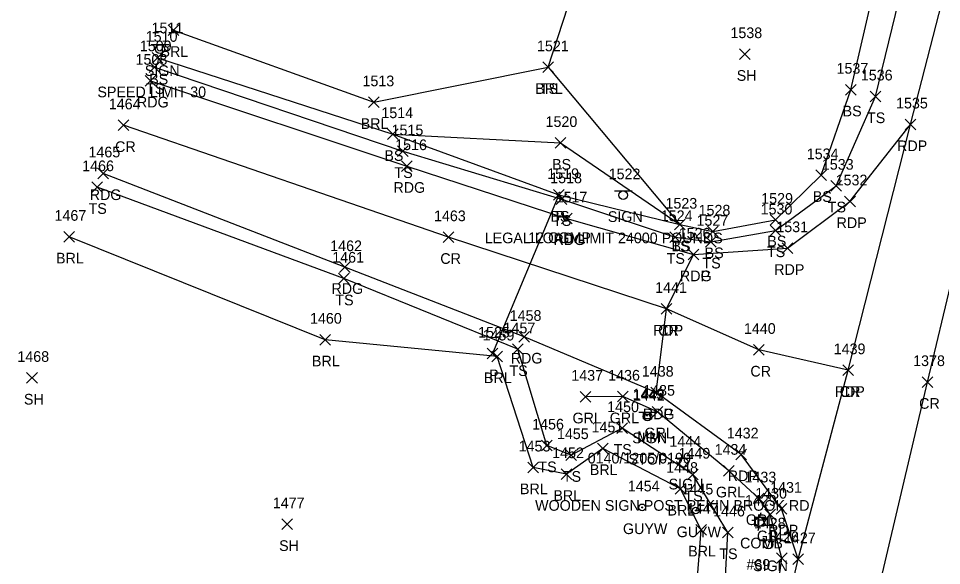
# Model space of a CAD drawing. Extents: x 1654425 to 1656893, y 667839 to 678429.
# Drawn here: x 1654452.9 to 1654625.8, y 668426.8 to 668529.4 of the extents above; entities that cross this region are included whole.
import ezdxf

# ---------------------------------------------------------------- set-up
doc = ezdxf.new("R2010")
doc.units = 0
for name, color, linetype in [('D_A', 7, 'Continuous'), ('D_I', 7, 'Continuous'), ('D_TIC', 7, 'Continuous'), ('DCP', 7, 'Continuous'), ('L_A', 7, 'Continuous'), ('L_C', 7, 'Continuous'), ('L_I', 7, 'Continuous'), ('L_TIC', 7, 'Continuous'), ('LABL', 7, 'Continuous'), ('LELB', 7, 'Continuous'), ('P_A', 7, 'Continuous'), ('P_I', 7, 'Continuous'), ('P_TIC', 7, 'Continuous'), ('PET', 7, 'Continuous'), ('PEU', 7, 'Continuous'), ('PRC', 7, 'Continuous'), ('R_A', 7, 'Continuous'), ('R_I', 7, 'Continuous'), ('R_TIC', 7, 'Continuous'), ('RGR', 7, 'Continuous'), ('S_A', 7, 'Continuous'), ('S_C', 7, 'Continuous'), ('S_I', 7, 'Continuous'), ('SRM', 7, 'Continuous'), ('SSGN', 7, 'Continuous'), ('U_A', 7, 'Continuous'), ('U_C', 7, 'Continuous'), ('U_I', 7, 'Continuous'), ('UP', 7, 'Continuous'), ('UPGW', 7, 'Continuous')]:
    doc.layers.add(name, color=color, linetype=linetype)

msp = doc.modelspace()

# ---------------------------------------------------------------- linework, layer by layer
at = {"layer": 'D_TIC'}
for points in [[(1654553.1, 668495.3), (1654555.1, 668497.3)], [(1654555.1, 668495.3), (1654553.1, 668497.3)], [(1654540.69, 668465.57), (1654542.69, 668467.57)], [(1654542.69, 668465.57), (1654540.69, 668467.57)]]:
    msp.add_lwpolyline(points, dxfattribs=at)
at = {"layer": 'DCP'}
msp.add_lwpolyline([(1654554.1, 668496.3), (1654541.69, 668466.57)], dxfattribs=at)
at = {"layer": 'L_TIC'}
for points in [[(1654480.96, 668526.19), (1654482.96, 668528.19)], [(1654482.96, 668526.19), (1654480.96, 668528.19)], [(1654477.94, 668521.02), (1654479.94, 668523.02)], [(1654479.94, 668521.02), (1654477.94, 668523.02)], [(1654587.96, 668521.7), (1654589.96, 668523.7)], [(1654589.96, 668521.7), (1654587.96, 668523.7)], [(1654477.4, 668519.24), (1654479.4, 668521.24)], [(1654479.4, 668519.24), (1654477.4, 668521.24)], [(1654551.15, 668519.24), (1654553.15, 668521.24)], [(1654553.15, 668519.24), (1654551.15, 668521.24)], [(1654551.15, 668519.24), (1654553.15, 668521.24)], [(1654553.15, 668519.24), (1654551.15, 668521.24)], [(1654607.84, 668515.04), (1654609.84, 668517.04)], [(1654609.84, 668515.04), (1654607.84, 668517.04)], [(1654612.45, 668513.77), (1654614.45, 668515.77)], [(1654614.45, 668513.77), (1654612.45, 668515.77)], [(1654518.46, 668512.68), (1654520.46, 668514.68)], [(1654520.46, 668512.68), (1654518.46, 668514.68)], [(1654522, 668506.7), (1654524, 668508.7)], [(1654524, 668506.7), (1654522, 668508.7)], [(1654522, 668506.7), (1654524, 668508.7)], [(1654524, 668506.7), (1654522, 668508.7)], [(1654553.42, 668505.05), (1654555.42, 668507.05)], [(1654555.42, 668505.05), (1654553.42, 668507.05)], [(1654523.92, 668503.49), (1654525.92, 668505.49)], [(1654525.92, 668503.49), (1654523.92, 668505.49)], [(1654602.26, 668499.01), (1654604.26, 668501.01)], [(1654604.26, 668499.01), (1654602.26, 668501.01)], [(1654466.62, 668496.76), (1654468.62, 668498.76)], [(1654468.62, 668496.76), (1654466.62, 668498.76)], [(1654605.09, 668497.04), (1654607.09, 668499.04)], [(1654607.09, 668497.04), (1654605.09, 668499.04)], [(1654553.1, 668495.3), (1654555.1, 668497.3)], [(1654555.1, 668495.3), (1654553.1, 668497.3)], [(1654553.63, 668494.51), (1654555.63, 668496.51)], [(1654555.63, 668494.51), (1654553.63, 668496.51)], [(1654575.79, 668489.74), (1654577.79, 668491.74)], [(1654577.79, 668489.74), (1654575.79, 668491.74)], [(1654575.79, 668489.74), (1654577.79, 668491.74)], [(1654577.79, 668489.74), (1654575.79, 668491.74)], [(1654575.79, 668489.74), (1654577.79, 668491.74)], [(1654577.79, 668489.74), (1654575.79, 668491.74)], [(1654593.74, 668490.66), (1654595.74, 668492.66)], [(1654595.74, 668490.66), (1654593.74, 668492.66)], [(1654582, 668488.45), (1654584, 668490.45)], [(1654584, 668488.45), (1654582, 668490.45)], [(1654593.71, 668488.65), (1654595.71, 668490.65)], [(1654595.71, 668488.65), (1654593.71, 668490.65)], [(1654461.39, 668487.47), (1654463.39, 668489.47)], [(1654463.39, 668487.47), (1654461.39, 668489.47)], [(1654574.92, 668487.4), (1654576.92, 668489.4)], [(1654576.92, 668487.4), (1654574.92, 668489.4)], [(1654581.62, 668486.53), (1654583.62, 668488.53)], [(1654583.62, 668486.53), (1654581.62, 668488.53)], [(1654512.85, 668479.62), (1654514.85, 668481.62)], [(1654514.85, 668479.62), (1654512.85, 668481.62)], [(1654509.33, 668468.18), (1654511.33, 668470.18)], [(1654511.33, 668468.18), (1654509.33, 668470.18)], [(1654545.47, 668466.37), (1654547.47, 668468.37)], [(1654547.47, 668466.37), (1654545.47, 668468.37)], [(1654541.55, 668465.03), (1654543.55, 668467.03)], [(1654543.55, 668465.03), (1654541.55, 668467.03)], [(1654454.43, 668461.02), (1654456.43, 668463.02)], [(1654456.43, 668461.02), (1654454.43, 668463.02)], [(1654564.96, 668451.6), (1654566.96, 668453.6)], [(1654566.96, 668451.6), (1654564.96, 668453.6)], [(1654550.88, 668448.34), (1654552.88, 668450.34)], [(1654552.88, 668448.34), (1654550.88, 668450.34)], [(1654561.38, 668447.81), (1654563.38, 668449.81)], [(1654563.38, 668447.81), (1654561.38, 668449.81)], [(1654555.46, 668446.54), (1654557.46, 668448.54)], [(1654557.46, 668446.54), (1654555.46, 668448.54)], [(1654548.29, 668444.22), (1654550.29, 668446.22)], [(1654550.29, 668444.22), (1654548.29, 668446.22)], [(1654554.56, 668442.97), (1654556.56, 668444.97)], [(1654556.56, 668442.97), (1654554.56, 668444.97)], [(1654578.25, 668442.89), (1654580.25, 668444.89)], [(1654580.25, 668442.89), (1654578.25, 668444.89)], [(1654575.94, 668440.22), (1654577.94, 668442.22)], [(1654577.94, 668440.22), (1654575.94, 668442.22)], [(1654502.23, 668433.58), (1654504.23, 668435.58)], [(1654504.23, 668433.58), (1654502.23, 668435.58)], [(1654579.8, 668432.54), (1654581.8, 668434.54)], [(1654581.8, 668432.54), (1654579.8, 668434.54)], [(1654584.78, 668432.05), (1654586.78, 668434.05)], [(1654586.78, 668432.05), (1654584.78, 668434.05)]]:
    msp.add_lwpolyline(points, dxfattribs=at)
at = {"layer": 'LABL'}
for points in [[(1654481.96, 668527.19), (1654519.46, 668513.68), (1654552.15, 668520.24), (1654557.67, 668537.4), (1654558.31, 668556.77)], [(1654577.73, 668393.9), (1654580.8, 668433.54), (1654576.94, 668441.22), (1654562.38, 668448.81), (1654555.56, 668443.97), (1654549.29, 668445.22), (1654542.55, 668466.03), (1654510.33, 668469.18), (1654462.39, 668488.47)]]:
    msp.add_lwpolyline(points, dxfattribs=at)
at = {"layer": 'LELB'}
for points in [[(1654478.4, 668520.24), (1654524.92, 668504.49), (1654554.63, 668495.51), (1654575.92, 668488.4), (1654582.62, 668487.53), (1654594.71, 668489.65), (1654606.09, 668498.04), (1654613.45, 668514.77), (1654621.57, 668548.1)], [(1654478.94, 668522.02), (1654523, 668507.7), (1654554.1, 668496.3), (1654576.79, 668490.74), (1654583, 668489.45), (1654594.74, 668491.66), (1654603.26, 668500.01), (1654608.84, 668516.04), (1654616.27, 668548.16)], [(1654552.15, 668520.24), (1654576.79, 668490.74)], [(1654523, 668507.7), (1654554.42, 668506.05), (1654576.79, 668490.74)], [(1654583.62, 668391.75), (1654585.78, 668433.05), (1654579.25, 668443.89), (1654565.96, 668452.6), (1654556.46, 668447.54), (1654551.88, 668449.34), (1654546.47, 668467.37), (1654513.85, 668480.62), (1654467.62, 668497.76)]]:
    msp.add_lwpolyline(points, dxfattribs=at)
at = {"layer": 'P_TIC'}
for points in [[(1654476.6, 668516.71), (1654478.6, 668518.71)], [(1654478.6, 668516.71), (1654476.6, 668518.71)], [(1654471.56, 668508.36), (1654473.56, 668510.36)], [(1654473.56, 668508.36), (1654471.56, 668510.36)], [(1654619, 668508.52), (1654621, 668510.52)], [(1654621, 668508.52), (1654619, 668510.52)], [(1654619, 668508.52), (1654621, 668510.52)], [(1654621, 668508.52), (1654619, 668510.52)], [(1654524.65, 668500.71), (1654526.65, 668502.71)], [(1654526.65, 668500.71), (1654524.65, 668502.71)], [(1654467.75, 668499.35), (1654469.75, 668501.35)], [(1654469.75, 668499.35), (1654467.75, 668501.35)], [(1654607.67, 668494.1), (1654609.67, 668496.1)], [(1654609.67, 668494.1), (1654607.67, 668496.1)], [(1654554.64, 668490.92), (1654556.64, 668492.92)], [(1654556.64, 668490.92), (1654554.64, 668492.92)], [(1654532.48, 668487.39), (1654534.48, 668489.39)], [(1654534.48, 668487.39), (1654532.48, 668489.39)], [(1654578.33, 668484.13), (1654580.33, 668486.13)], [(1654580.33, 668484.13), (1654578.33, 668486.13)], [(1654578.33, 668484.13), (1654580.33, 668486.13)], [(1654580.33, 668484.13), (1654578.33, 668486.13)], [(1654595.99, 668485.33), (1654597.99, 668487.33)], [(1654597.99, 668485.33), (1654595.99, 668487.33)], [(1654513.04, 668481.77), (1654515.04, 668483.77)], [(1654515.04, 668481.77), (1654513.04, 668483.77)], [(1654573.3, 668473.95), (1654575.3, 668475.95)], [(1654575.3, 668473.95), (1654573.3, 668475.95)], [(1654573.3, 668473.95), (1654575.3, 668475.95)], [(1654575.3, 668473.95), (1654573.3, 668475.95)], [(1654546.62, 668468.71), (1654548.62, 668470.71)], [(1654548.62, 668468.71), (1654546.62, 668470.71)], [(1654590.58, 668466.27), (1654592.58, 668468.27)], [(1654592.58, 668466.27), (1654590.58, 668468.27)], [(1654607.32, 668462.46), (1654609.32, 668464.46)], [(1654609.32, 668462.46), (1654607.32, 668464.46)], [(1654607.32, 668462.46), (1654609.32, 668464.46)], [(1654609.32, 668462.46), (1654607.32, 668464.46)], [(1654622.19, 668460.23), (1654624.19, 668462.23)], [(1654624.19, 668460.23), (1654622.19, 668462.23)], [(1654571.38, 668458.25), (1654573.38, 668460.25)], [(1654573.38, 668458.25), (1654571.38, 668460.25)], [(1654571.38, 668458.25), (1654573.38, 668460.25)], [(1654573.38, 668458.25), (1654571.38, 668460.25)], [(1654587.29, 668446.66), (1654589.29, 668448.66)], [(1654589.29, 668446.66), (1654587.29, 668448.66)], [(1654594.84, 668436.49), (1654596.84, 668438.49)], [(1654596.84, 668436.49), (1654594.84, 668438.49)], [(1654597.99, 668427.03), (1654599.99, 668429.03)], [(1654599.99, 668427.03), (1654597.99, 668429.03)], [(1654597.99, 668427.03), (1654599.99, 668429.03)], [(1654599.99, 668427.03), (1654597.99, 668429.03)]]:
    msp.add_lwpolyline(points, dxfattribs=at)
at = {"layer": 'PET'}
for points in [[(1654621.12, 668380.08), (1654605.24, 668384.01), (1654589.51, 668387.16), (1654598.99, 668428.03), (1654608.32, 668463.46), (1654620, 668509.52), (1654636.49, 668573.63), (1654648.24, 668612.9), (1654659.58, 668647.93)], [(1654598.99, 668428.03), (1654595.84, 668437.49), (1654588.29, 668447.66), (1654572.38, 668459.25), (1654574.3, 668474.95), (1654579.33, 668485.13), (1654596.99, 668486.33), (1654608.67, 668495.1), (1654620, 668509.52)]]:
    msp.add_lwpolyline(points, dxfattribs=at)
at = {"layer": 'PEU'}
for points in [[(1654477.6, 668517.71), (1654525.65, 668501.71), (1654555.64, 668491.92), (1654579.33, 668485.13)], [(1654572.38, 668459.25), (1654547.62, 668469.71), (1654514.04, 668482.77), (1654468.75, 668500.35)]]:
    msp.add_lwpolyline(points, dxfattribs=at)
at = {"layer": 'PRC'}
for points in [[(1654605.24, 668384.01), (1654612.68, 668416.68), (1654623.19, 668461.23), (1654632.58, 668500.46), (1654641.79, 668536.76), (1654650.75, 668570.78), (1654657.62, 668594.43), (1654672.71, 668645.31)], [(1654608.32, 668463.46), (1654591.58, 668467.27), (1654574.3, 668474.95), (1654533.48, 668488.39), (1654472.56, 668509.36)]]:
    msp.add_lwpolyline(points, dxfattribs=at)
at = {"layer": 'R_TIC'}
for points in [[(1654558.15, 668457.49), (1654560.15, 668459.49)], [(1654560.15, 668457.49), (1654558.15, 668459.49)], [(1654565.11, 668457.51), (1654567.11, 668459.51)], [(1654567.11, 668457.51), (1654565.11, 668459.51)], [(1654571.63, 668454.68), (1654573.63, 668456.68)], [(1654573.63, 668454.68), (1654571.63, 668456.68)], [(1654585, 668443.61), (1654587, 668445.61)], [(1654587, 668443.61), (1654585, 668445.61)], [(1654590.61, 668438.43), (1654592.61, 668440.43)], [(1654592.61, 668438.43), (1654590.61, 668440.43)], [(1654592.7, 668435.39), (1654594.7, 668437.39)], [(1654594.7, 668435.39), (1654592.7, 668437.39)], [(1654594.88, 668427.22), (1654596.88, 668429.22)], [(1654596.88, 668427.22), (1654594.88, 668429.22)]]:
    msp.add_lwpolyline(points, dxfattribs=at)
at = {"layer": 'RGR'}
msp.add_lwpolyline([(1654588.77, 668387.95), (1654594.16, 668415.33), (1654595.88, 668428.22), (1654593.7, 668436.39), (1654591.61, 668439.43), (1654586, 668444.61), (1654572.63, 668455.68), (1654566.11, 668458.51), (1654559.15, 668458.49)], dxfattribs=at)
at = {"layer": 'SRM'}
msp.add_lwpolyline([(1654570, 668455.59), (1654571.25, 668455.59), (1654571.25, 668454.34), (1654570, 668454.34)], close=True, dxfattribs=at)
msp.add_circle((1654570.63, 668454.97), 0.0833, dxfattribs=at)
at = {"layer": 'SSGN'}
for p, q in [((1654477.76, 668524.48), (1654481.1, 668524.48)), ((1654479.41, 668523.64), (1654479.41, 668523.64)), ((1654564.53, 668497.1), (1654567.86, 668497.1)), ((1654566.18, 668496.27), (1654566.18, 668496.27)), ((1654569.09, 668455.62), (1654572.42, 668455.62)), ((1654570.73, 668454.78), (1654570.73, 668454.78)), ((1654575.91, 668446.96), (1654579.24, 668446.96)), ((1654577.55, 668446.13), (1654577.55, 668446.13)), ((1654591.72, 668431.64), (1654595.06, 668431.64)), ((1654593.37, 668430.81), (1654593.37, 668430.81))]:
    msp.add_line(p, q, dxfattribs=at)
for centre in [(1654479.41, 668523.64), (1654566.18, 668496.27), (1654570.73, 668454.78), (1654577.55, 668446.13), (1654593.37, 668430.81)]:
    msp.add_circle(centre, 0.833, dxfattribs=at)
at = {"layer": 'UP'}
for p, q in [((1654591.94, 668436.72), (1654591.69, 668435.88)), ((1654590.86, 668434.22), (1654590.86, 668435.88)), ((1654590.86, 668435.88), (1654592.52, 668435.88)), ((1654591.69, 668435.05), (1654591.69, 668435.05)), ((1654592.52, 668435.88), (1654592.52, 668434.22)), ((1654592.52, 668434.22), (1654590.86, 668434.22)), ((1654591.44, 668433.38), (1654591.69, 668434.22))]:
    msp.add_line(p, q, dxfattribs=at)
msp.add_circle((1654591.69, 668435.05), 0.833, dxfattribs=at)
at = {"layer": 'UPGW'}
for centre, radius in [((1654569.75, 668437.74), 0.625), ((1654569.75, 668437.74), 0.0833), ((1654579.81, 668437.16), 0.625), ((1654579.81, 668437.16), 0.0833)]:
    msp.add_circle(centre, radius, dxfattribs=at)

# ---------------------------------------------------------------- texts
at = {"layer": 'D_A'}
for p in [(1654553.47, 668491.3), (1654541.07, 668461.57)]:
    msp.add_text('P', height=2, dxfattribs=at).set_placement(p)
at = {"layer": 'D_I'}
for s, p in [('1519', (1654551.96, 668499.3)), ('1525', (1654539, 668469.57))]:
    msp.add_text(s, height=2, dxfattribs=at).set_placement(p)
at = {"layer": 'L_A'}
for s, p in [('BRL', (1654479.5, 668522.19)), ('BS', (1654477.38, 668517.02)), ('SH', (1654587.45, 668517.7)), ('TS', (1654476.81, 668515.24)), ('BRL', (1654549.69, 668515.24)), ('TS', (1654550.56, 668515.24)), ('BS', (1654607.28, 668511.04)), ('BRL', (1654517.01, 668508.68)), ('TS', (1654611.86, 668509.77)), ('BS', (1654521.44, 668502.7)), ('BS', (1654521.44, 668502.7)), ('BS', (1654552.86, 668501.05)), ('TS', (1654523.33, 668499.49)), ('BS', (1654601.7, 668495.01)), ('TS', (1654466.03, 668492.76)), ('TS', (1654604.5, 668493.04)), ('BS', (1654552.54, 668491.3)), ('TS', (1654553.04, 668490.51)), ('BS', (1654593.18, 668486.66)), ('TS', (1654575.2, 668485.74)), ('BS', (1654575.23, 668485.74)), ('BS', (1654575.23, 668485.74)), ('BS', (1654581.44, 668484.45)), ('TS', (1654593.12, 668484.65)), ('BRL', (1654459.93, 668483.47)), ('TS', (1654574.33, 668483.4)), ('TS', (1654581.03, 668482.53)), ('TS', (1654512.26, 668475.62)), ('BRL', (1654507.87, 668464.18)), ('TS', (1654544.88, 668462.37)), ('BRL', (1654540.09, 668461.03)), ('SH', (1654453.92, 668457.02)), ('TS', (1654564.37, 668447.6)), ('TS', (1654550.29, 668444.34)), ('BRL', (1654559.93, 668443.81)), ('TS', (1654554.87, 668442.54)), ('BRL', (1654546.84, 668440.22)), ('BRL', (1654553.11, 668438.97)), ('TS', (1654577.66, 668438.89)), ('BRL', (1654574.48, 668436.22)), ('SH', (1654501.72, 668429.58)), ('BRL', (1654578.35, 668428.54)), ('TS', (1654584.19, 668428.05))]:
    msp.add_text(s, height=2, dxfattribs=at).set_placement(p)
at = {"layer": 'L_C'}
msp.add_text('12 CGMP', height=2, dxfattribs=at).set_placement((1654548.39, 668487.3))
at = {"layer": 'L_I'}
for s, p in [('1538', (1654586.27, 668525.7)), ('1510', (1654476.73, 668525.02)), ('1509', (1654475.63, 668523.24)), ('1521', (1654550.03, 668523.24)), ('1521', (1654550.03, 668523.24)), ('1537', (1654606.15, 668519.04)), ('1536', (1654610.7, 668517.77)), ('1513', (1654517.34, 668516.68)), ('1514', (1654520.88, 668510.7)), ('1514', (1654520.88, 668510.7)), ('1520', (1654551.64, 668509.05)), ('1515', (1654522.79, 668507.49)), ('1534', (1654600.57, 668503.01)), ('1466', (1654464.83, 668500.76)), ('1533', (1654603.4, 668501.04)), ('1519', (1654551.96, 668499.3)), ('1518', (1654552.51, 668498.51)), ('1529', (1654592.04, 668494.66)), ('1523', (1654574.1, 668493.74)), ('1523', (1654574.1, 668493.74)), ('1523', (1654574.1, 668493.74)), ('1467', (1654459.65, 668491.47)), ('1524', (1654573.22, 668491.4)), ('1528', (1654580.31, 668492.45)), ('1530', (1654591.93, 668492.65)), ('1527', (1654579.92, 668490.53)), ('1461', (1654511.68, 668483.62)), ('1460', (1654507.51, 668472.18)), ('1457', (1654543.77, 668470.37)), ('1459', (1654539.85, 668469.03)), ('1468', (1654452.69, 668465.02)), ('1450', (1654563.18, 668455.6)), ('1456', (1654549.13, 668452.34)), ('1451', (1654560.26, 668451.81)), ('1455', (1654553.77, 668450.54)), ('1453', (1654546.6, 668448.22)), ('1452', (1654552.87, 668446.97)), ('1449', (1654576.55, 668446.89)), ('1448', (1654574.24, 668444.22)), ('1477', (1654500.54, 668437.58)), ('1447', (1654578.11, 668436.54)), ('1446', (1654583.03, 668436.05))]:
    msp.add_text(s, height=2, dxfattribs=at).set_placement(p)
at = {"layer": 'P_A'}
for s, p in [('RDG', (1654475.09, 668512.71)), ('CR', (1654470.99, 668504.36)), ('RDP', (1654617.49, 668504.52)), ('RDP', (1654617.49, 668504.52)), ('RDG', (1654523.14, 668496.71)), ('RDG', (1654466.24, 668495.35)), ('RDP', (1654606.16, 668490.1)), ('RDG', (1654553.13, 668486.92)), ('CR', (1654531.92, 668483.39)), ('RDP', (1654594.48, 668481.33)), ('RDG', (1654576.81, 668480.13)), ('RDP', (1654576.81, 668480.13)), ('RDG', (1654511.53, 668477.77)), ('RDP', (1654571.79, 668469.95)), ('CR', (1654572.73, 668469.95)), ('RDG', (1654545.11, 668464.71)), ('CR', (1654590.01, 668462.27)), ('RDP', (1654605.8, 668458.46)), ('CR', (1654606.75, 668458.46)), ('CR', (1654621.62, 668456.23)), ('RDG', (1654569.86, 668454.25)), ('RDP', (1654569.86, 668454.25)), ('RDP', (1654585.77, 668442.66)), ('RDP', (1654593.33, 668432.49))]:
    msp.add_text(s, height=2, dxfattribs=at).set_placement(p)
at = {"layer": 'P_I'}
for s, p in [('1508', (1654474.83, 668520.71)), ('1464', (1654469.82, 668512.36)), ('1535', (1654617.3, 668512.52)), ('1535', (1654617.3, 668512.52)), ('1465', (1654466.01, 668503.35)), ('1516', (1654523.47, 668504.71)), ('1532', (1654605.98, 668498.1)), ('1517', (1654553.52, 668494.92)), ('1463', (1654530.74, 668491.39)), ('1531', (1654594.87, 668489.33)), ('1526', (1654576.58, 668488.13)), ('1526', (1654576.58, 668488.13)), ('1462', (1654511.3, 668485.77)), ('1441', (1654572.17, 668477.95)), ('1441', (1654572.17, 668477.95)), ('1458', (1654544.92, 668472.71)), ('1440', (1654588.8, 668470.27)), ('1439', (1654605.62, 668466.46)), ('1439', (1654605.62, 668466.46)), ('1378', (1654620.5, 668464.23)), ('1438', (1654569.68, 668462.25)), ('1438', (1654569.68, 668462.25)), ('1432', (1654585.59, 668450.66)), ('1431', (1654593.71, 668440.49)), ('1427', (1654596.3, 668431.03)), ('1427', (1654596.3, 668431.03))]:
    msp.add_text(s, height=2, dxfattribs=at).set_placement(p)
at = {"layer": 'R_A'}
for p in [(1654556.69, 668453.49), (1654563.66, 668453.51), (1654570.17, 668450.68), (1654583.55, 668439.61), (1654589.15, 668434.43), (1654591.24, 668431.39)]:
    msp.add_text('GRL', height=2, dxfattribs=at).set_placement(p)
at = {"layer": 'R_I'}
for s, p in [('1437', (1654556.46, 668461.49)), ('1436', (1654563.37, 668461.51)), ('1435', (1654569.93, 668458.68)), ('1434', (1654583.31, 668447.61)), ('1433', (1654588.91, 668442.43)), ('1430', (1654590.92, 668439.39)), ('1426', (1654593.13, 668431.22))]:
    msp.add_text(s, height=2, dxfattribs=at).set_placement(p)
at = {"layer": 'S_A'}
for s, p in [('SIGN', (1654476.55, 668518.62)), ('SIGN', (1654563.31, 668491.25)), ('SIGN', (1654567.87, 668449.76)), ('MM', (1654568.82, 668449.97)), ('SIGN', (1654574.69, 668441.11)), ('SIGN', (1654590.51, 668425.79))]:
    msp.add_text(s, height=2, dxfattribs=at).set_placement(p)
at = {"layer": 'S_C'}
for s, p in [('SPEED LIMIT 30', (1654467.68, 668514.62)), ('LEGAL LOAD LIMIT 24000 POUNDS', (1654540.24, 668487.25)), ('0140/1205/0190', (1654559.53, 668445.97)), ('STOP', (1654567.19, 668445.76)), ('WOODEN SIGN POST PEKIN BROOK RD', (1654549.68, 668437.11))]:
    msp.add_text(s, height=2, dxfattribs=at).set_placement(p)
at = {"layer": 'S_I'}
for s, p in [('1511', (1654477.83, 668526.62)), ('1522', (1654563.46, 668499.25)), ('1443', (1654567.94, 668457.97)), ('1442', (1654568.02, 668457.76)), ('1444', (1654574.84, 668449.11)), ('1428', (1654590.66, 668433.79))]:
    msp.add_text(s, height=2, dxfattribs=at).set_placement(p)
at = {"layer": 'U_A'}
for s, p in [('GUYW', (1654566.14, 668432.74)), ('GUYW', (1654576.2, 668432.16)), ('COMB', (1654588.08, 668430.05))]:
    msp.add_text(s, height=2, dxfattribs=at).set_placement(p)
at = {"layer": 'U_C'}
msp.add_text('#69', height=2, dxfattribs=at).set_placement((1654589.27, 668426.05))
at = {"layer": 'U_I'}
for s, p in [('1454', (1654567.05, 668440.74)), ('1445', (1654577.11, 668440.16)), ('1429', (1654588.99, 668438.05))]:
    msp.add_text(s, height=2, dxfattribs=at).set_placement(p)

doc.saveas('drawing.dxf')
